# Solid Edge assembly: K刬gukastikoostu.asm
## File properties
Author: Türk
Template: Iso Assembly.asm
Last saved by: Türk
Revision: 22
Application: Solid Edge
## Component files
ljakaas.par
igukasti kaas2.par
igukand.par
igukanginupp.par
korpus.par
ellaager_R22.asm
llikoostu.asm
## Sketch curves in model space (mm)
circle centre (0, -545, 0) radius 22
circle centre (0, -545, -60) radius 22
circle centre (0, -545, 0) radius 22
line (-100, -545, 0) -> (-100, -545, -50)
arc centre (-40, -545, -50) radius 60 from (-100, -545, -50) through (-81.1745, -545, -93.6424) to (-40, -545, -110)
line (-40, -545, -110) -> (40, -545, -110)
arc centre (40, -545, -50) radius 60 from (40, -545, -110) through (83.6424, -545, -91.1745) to (100, -545, -50)
line (100, -545, -50) -> (100, -545, 0)
line (100, -545, 0) -> (64, -545, 48)
arc centre (0, -545, 0) radius 80 from (64, -545, 48) through (-2.3927, -545, 79.9642) to (-64, -545, 48)
line (-64, -545, 48) -> (-100, -545, 0)
line (-64, -535, 48) -> (-100, -535, 0)
line (-100, -535, 0) -> (-93.75, -535, 0)
line (-60, -535, 45) -> (-93.75, -535, 0)
arc centre (0, -535, 0) radius 75 from (60, -535, 45) through (-2.2431, -535, 74.9664) to (-60, -535, 45)
line (93.75, -535, 0) -> (60, -535, 45)
line (93.75, -535, 0) -> (100, -535, 0)
line (64, -535, 48) -> (100, -535, 0)
arc centre (0, -535, 0) radius 80 from (64, -535, 48) through (-2.3927, -535, 79.9642) to (-64, -535, 48)
line (95, -190, 0) -> (100, -190, 0)
arc centre (0, -190, 0) radius 95 from (-95, -190, 0) through (2.8152, -190, 94.9583) to (95, -190, 0)
line (-100, -190, 0) -> (-95, -190, 0)
arc centre (0, -190, 0) radius 100 from (-100, -190, 0) through (2.9633, -190, 99.9561) to (100, -190, 0)
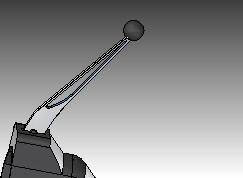
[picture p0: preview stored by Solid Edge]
